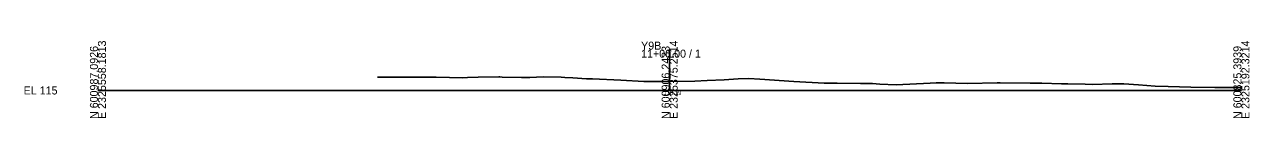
# Model space of a CAD drawing. Extents: x -26 to 3203, y 990 to 2017.
# Drawn here: x -25.7 to 402.8, y 1990.3 to 2017.4 of the extents above; entities that cross this region are included whole.
import ezdxf

# ---------------------------------------------------------------- set-up
doc = ezdxf.new("R2010")
doc.units = 0
for name, color, linetype in [('Default', 7, 'Continuous'), ('Exist CMT Pavement', 7, 'Continuous'), ('Exist Cross Section Cell', 7, 'Continuous'), ('Exist XS Center Line Elevation Label', 7, 'Continuous'), ('Exist XS Ground Line', 7, 'Continuous'), ('Prop XS Earthwork Shape', 7, 'Continuous')]:
    doc.layers.add(name, color=color, linetype=linetype)

msp = doc.modelspace()

# ---------------------------------------------------------------- linework, layer by layer
at = {"layer": 'Exist CMT Pavement'}
msp.add_lwpolyline([(200, 2003.19), (200, 2003.29), (200.1, 2003.29), (200.1, 2003.19)], dxfattribs=at)
at = {"layer": 'Exist Cross Section Cell'}
for p, q in [((200, 2000), (200, 2014.29)), ((0, 2000), (200, 2000)), ((200, 2000), (400, 2000))]:
    msp.add_line(p, q, dxfattribs=at)
at = {"layer": 'Exist XS Ground Line'}
msp.add_lwpolyline([(97.75, 2004.62), (112.56, 2004.7), (118.33, 2004.64), (127.64, 2004.43), (129.26, 2004.52), (132.98, 2004.63), (140.2, 2004.73), (140.56, 2004.73), (141.39, 2004.7), (148.15, 2004.52), (151.13, 2004.53), (155.73, 2004.76), (162.07, 2004.63), (163.31, 2004.55), (166.13, 2004.37), (170.9, 2004.11), (173, 2004.02), (182.88, 2003.62), (190.96, 2003.1), (199.69, 2003.19), (200, 2003.19), (208.83, 2003.25), (213.08, 2003.44), (219.09, 2003.74), (223.98, 2004.1), (227.67, 2004.15), (231.56, 2004.01), (243.48, 2003.11), (254.03, 2002.61), (258.56, 2002.56), (266.8, 2002.45), (271, 2002.39), (273.57, 2002.26), (279.29, 2002.01), (291.12, 2002.54), (293.28, 2002.66), (296.01, 2002.63), (304.22, 2002.47), (314.58, 2002.65), (315.15, 2002.66), (315.6, 2002.66), (326.08, 2002.6), (330.14, 2002.55), (337.02, 2002.35), (337.72, 2002.34), (339.32, 2002.3), (345.31, 2002.17), (347.95, 2002.13), (354.79, 2002.28), (358.89, 2002.33), (364.06, 2001.97), (369.82, 2001.52), (374.39, 2001.37), (382.33, 2001.15), (390.66, 2001), (399.35, 2000.98), (400, 2000.98)], dxfattribs=at)
at = {"layer": 'Prop XS Earthwork Shape'}
msp.add_lwpolyline([(200, 2003.19), (200, 2003.29), (200.1, 2003.29), (200.1, 2003.19)], close=True, dxfattribs=at)

# ---------------------------------------------------------------- texts
at = {"layer": 'Default'}
msp.add_text('-', height=0.0001, dxfattribs=at).set_placement((0, 2000))
at = {"layer": 'Exist Cross Section Cell'}
for s, p in [('N 600987.0926', (0, 1990)), ('E 2325558.1813', (2.8, 1990)), ('N 600906.2433', (200, 1990)), ('E 2325375.2514', (202.8, 1990)), ('N 600825.3939', (400, 1990)), ('E 2325192.3214', (402.8, 1990))]:
    msp.add_text(s, height=2.8, rotation=90, dxfattribs=at).set_placement(p)
for s, p in [('Y9B', (190, 2014.29)), ('11+00.00 / 1', (190, 2011.49)), ('EL 115', (-26, 1998.6))]:
    msp.add_text(s, height=2.8, dxfattribs=at).set_placement(p)
at = {"layer": 'Exist XS Center Line Elevation Label'}
msp.add_text('118.19', height=1.5, dxfattribs=at).set_placement((197.79, 1998.44))

doc.saveas('drawing.dxf')
